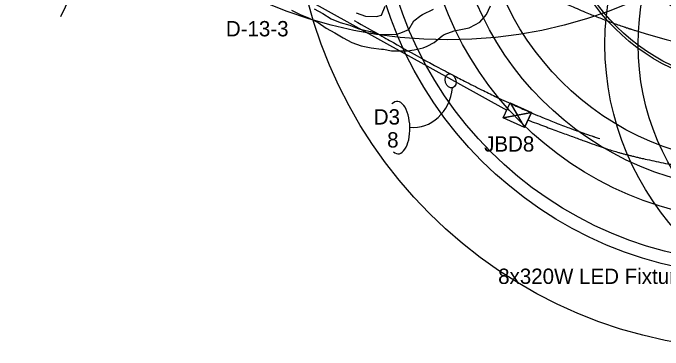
# Model space of a CAD drawing. Extents: x 1638506 to 1658005, y 834807 to 846788.
# Drawn here: x 1640712 to 1641220, y 841908 to 842171 of the extents above; entities that cross this region are included whole.
import ezdxf

# ---------------------------------------------------------------- set-up
doc = ezdxf.new("R2010")
doc.units = 0
for name, color, linetype in [('Default', 7, 'Continuous'), ('Old_Level_1', 7, 'Continuous'), ('Old_Level_2', 7, 'Continuous'), ('Old_Level_4', 7, 'Continuous'), ('Scratch_Level_0', 7, 'Continuous')]:
    doc.layers.add(name, color=color, linetype=linetype)

msp = doc.modelspace()

# ---------------------------------------------------------------- linework, layer by layer
at = {"layer": 'Default'}
for p, q in [((1640921.33, 842193.61), (1641098.15, 842095.33)), ((1641100.87, 842101.21), (1641112.02, 842081.77)), ((1641095.43, 842089.45), (1641117.47, 842093.53))]:
    msp.add_line(p, q, dxfattribs=at)
for points in [[(1641100.87, 842101.21), (1641117.47, 842093.53), (1641112.02, 842081.77), (1641095.43, 842089.45)], [(1641106.45, 842091.49), (1641095.43, 842089.45), (1641100.87, 842101.21)], [(1641106.45, 842091.49), (1641112.02, 842081.77), (1641117.47, 842093.53)]]:
    msp.add_lwpolyline(points, close=True, dxfattribs=at)
msp.add_ellipse((1641054.15, 842118.38), major_axis=(-1.72, 5.4), ratio=0.730797, dxfattribs=at)
for centre, major_axis, ratio, start_param, end_param in [((1641026.09, 842116.34), (3.78, 34.34), 0.862742, 3.141593, 4.712389), ((1641012.74, 842081.78), (0.49, -20.52), 0.466223, 1.570796, 3.572354), ((1641012.74, 842081.78), (0.49, -20.52), 0.466223, 5.884886, 7.853982)]:
    msp.add_ellipse(centre, major_axis=major_axis, ratio=ratio, start_param=start_param, end_param=end_param, dxfattribs=at)
msp.add_open_spline([(1641114.75, 842087.65), (1641168.01, 842067.62), (1641198.18, 842058.54), (1641257.4, 842046.88), (1641278.73, 842044.73), (1641337.02, 842041.51), (1641390.03, 842042.51)], degree=2, dxfattribs=at)
at = {"layer": 'Old_Level_1'}
for radius in [365, 307, 240, 158]:
    msp.add_circle((1641295.68, 842272.71), radius, dxfattribs=at)
at = {"layer": 'Old_Level_2'}
msp.add_line((1640859.16, 842396.17), (1640748.91, 842168.53), dxfattribs=at)
msp.add_arc((1641332.1, 842574.94), 438, 252.1948, 287.7872, dxfattribs=at)
for points in [[(1641022.96, 842242.94), (1641038.01, 842234.35), (1641052.83, 842225.89), (1641082.21, 842209.62), (1641096.78, 842201.8), (1641118.55, 842190.83), (1641125.8, 842187.29), (1641140.28, 842180.52), (1641147.52, 842177.28), (1641161.99, 842171.13), (1641169.22, 842168.22), (1641180.07, 842164.14), (1641183.68, 842162.83), (1641189.11, 842160.94), (1641190.91, 842160.32), (1641192.94, 842159.64), (1641193.17, 842159.56), (1641193.42, 842159.48), (1641193.43, 842159.48), (1641193.44, 842159.47), (1641193.46, 842159.47), (1641193.5, 842159.45), (1641193.54, 842159.44), (1641193.61, 842159.42), (1641193.66, 842159.4), (1641193.71, 842159.38), (1641193.72, 842159.38), (1641193.74, 842159.37), (1641193.76, 842159.37), (1641193.81, 842159.35), (1641193.92, 842159.31), (1641194, 842159.29), (1641194.16, 842159.23), (1641194.27, 842159.2), (1641194.48, 842159.13), (1641194.81, 842159.02), (1641195.15, 842158.91), (1641196.3, 842158.53), (1641197.27, 842158.21), (1641198.3, 842157.88)], [(1640978.83, 842165.65), (1640994.06, 842156.96), (1641009.35, 842148.23), (1641032.54, 842135.39), (1641040.31, 842131.16), (1641055.97, 842122.82), (1641063.85, 842118.73), (1641079.75, 842110.73), (1641087.77, 842106.82), (1641103.95, 842099.26), (1641112.12, 842095.61), (1641128.63, 842088.61), (1641136.96, 842085.26), (1641149.59, 842080.52), (1641153.82, 842078.99), (1641160.2, 842076.76), (1641162.6, 842075.94), (1641165.01, 842075.14), (1641165.41, 842075), (1641165.55, 842074.96), (1641165.82, 842074.87), (1641166.49, 842074.64), (1641167.16, 842074.42), (1641168.77, 842073.9), (1641169.82, 842073.55), (1641170.86, 842073.22)]]:
    msp.add_open_spline(points, degree=3, dxfattribs=at)
at = {"layer": 'Old_Level_4'}
for centre, radius in [((1641051.91, 842515.45), 365), ((1641538.84, 842469.72), 365), ((1641393.92, 842146.92), 219), ((1641393.92, 842146.92), 193)]:
    msp.add_circle(centre, radius, dxfattribs=at)
at = {"layer": 'Scratch_Level_0'}
for points in [[(1640929.77, 842173.82), (1640936.6, 842170.37), (1640943.64, 842167.33), (1640950.53, 842163.99), (1640956.86, 842159.58), (1640963.53, 842155.83), (1640970.13, 842151.95), (1640976.93, 842148.43), (1640984.16, 842145.76), (1640991.91, 842144.09), (1641000.12, 842143.29), (1641001.61, 842143.1), (1641008.02, 842141.91), (1641016.58, 842141.79), (1641020.49, 842141.92), (1641025.59, 842142.54), (1641032.75, 842144.17), (1641035.8, 842145.6), (1641041.39, 842148.3), (1641047.62, 842153.68), (1641049.07, 842154.56), (1641056.95, 842157.46), (1641059.49, 842158.02), (1641068.78, 842159.94), (1641069.23, 842160.18), (1641077.03, 842164.27), (1641082.25, 842170.18), (1641085.43, 842177.15)], [(1640947.48, 842174.72), (1640954.26, 842171.18), (1640960.7, 842166.99), (1640967.83, 842164.12), (1640975.29, 842161.89), (1640982.39, 842158.96), (1640990.14, 842157.27), (1640991.6, 842156.92), (1640997.6, 842155.04), (1641005.96, 842154.55), (1641012.14, 842154.87), (1641015.37, 842156.06), (1641021.43, 842158.67), (1641025.38, 842165.24), (1641030.98, 842169.52), (1641032.25, 842170.29), (1641040.72, 842174.51)], [(1640980.29, 842171.49), (1640987.63, 842169.04), (1640996.12, 842168.79), (1641000.03, 842169.78), (1641002.99, 842176.87)]]:
    msp.add_lwpolyline(points, dxfattribs=at)
for radius in [297, 264, 219, 160, 118]:
    msp.add_circle((1641295.75, 842272.71), radius, dxfattribs=at)

# ---------------------------------------------------------------- texts
at = {"layer": 'Default'}
for s, p in [('D-13-3', (1640878.34, 842153.19)), ('D3', (1640994.08, 842084.18)), ('8', (1641004.54, 842066.18)), ('JBD8', (1641080.41, 842063))]:
    msp.add_text(s, height=12, dxfattribs=at).set_placement(p)
at = {"layer": 'Scratch_Level_0'}
msp.add_text('8x320W LED Fixtures', height=12, dxfattribs=at).set_placement((1641091.39, 841959.43))

doc.saveas('drawing.dxf')
